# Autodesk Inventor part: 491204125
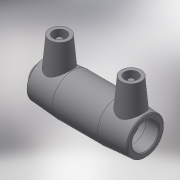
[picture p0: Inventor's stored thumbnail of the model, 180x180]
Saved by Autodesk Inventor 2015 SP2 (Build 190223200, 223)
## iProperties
Created: 2017-06
Part Number: 491204125
Material: Generic
Description: PLASSON END CAP 125
Document SubType Name: Modeling
Designer: KIM
Mass: 38.9236 g
Surface Area: 152.394 cm^2
Volume: 38.9236 cm^3
Density: 1 g/cm^3
Appearance: Default
Author: KIM
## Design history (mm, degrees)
derived "491204.ipt"
feature "Solid1::491204.ipt"
tag "TaggingFeature1"
body "Solid1"
other parameters: "d0" = 173, "d1" = 125, "d2" = 157, "d3" = 85, "d4" = 55.5, "d5" = 141.3, "d6" = 118.75, "d7" = 125, "d8" = 168 deg, "d10" = 34, "d11" = 11.33333, "d13" = 177.6, "d14" = 17.6296, "d15" = 85, "d16" = 85, "d17" = 118.75, "d18" = 125, "d19" = 3.52592, "d20" = 168 deg, "d22" = 147.58, "d23" = 157, "d24" = 143.1526, "d25" = 135 deg, "d26" = 79.92, "d27" = 135 deg, "d29" = 87, "d30" = 15, "d31" = 71.04, "d34" = 5 deg, "d35" = 15, "d39" = 5 deg, "d41" = 4, "d42" = 14, "d43" = 0, "d45" = 4, "d46" = 14, "d47" = 0, "d48" = 222, "d49" = 1, "d52" = 3.996, "d53" = 137.5, "d54" = 3.996, "d56" = 12.5, "d57" = 3.75, "d60" = 33.3, "d61" = 2.5, "d63" = 222, "d64" = 1, "d67" = 25, "d68" = 137.5, "d69" = 4.44, "d70" = 0, "d71" = 3.996, "d72" = 3, "d73" = 0, "d74" = 24.65, "d75" = 8.21667, "d76" = 3, "d77" = 0, "d_" = 125, "L_" = 222, "L_1" = 85, "D_" = 157, "A_" = 87, "d_2" = 12, "L_0" = 173, "d55" = 12.5
